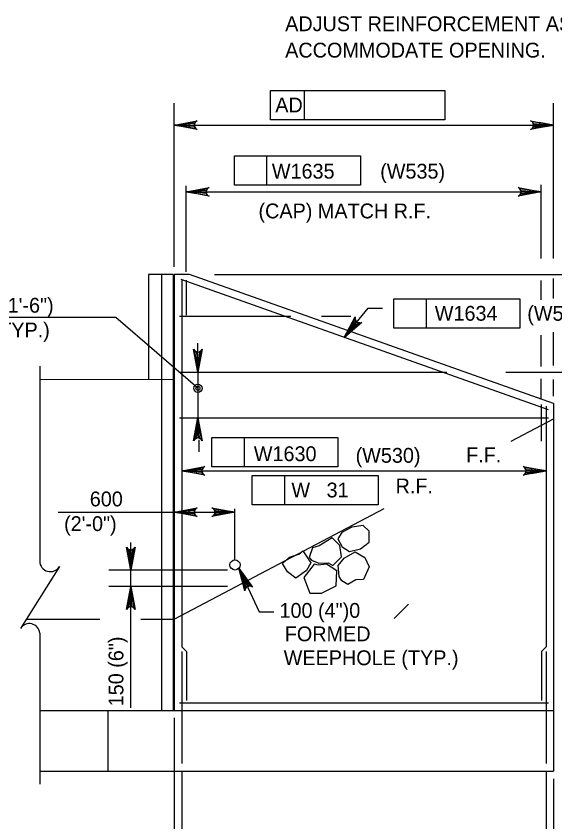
# Model space of a CAD drawing. Extents: x 638340 to 640241, y 295465 to 298435.
# Drawn here: x 638795.5 to 638904.7, y 296169.9 to 296333.1 of the extents above; entities that cross this region are included whole.
import ezdxf

# ---------------------------------------------------------------- set-up
doc = ezdxf.new("R2010")
doc.units = 0
for name, color, linetype in [('10', 7, 'Continuous'), ('3', 7, 'Continuous'), ('4', 7, 'Continuous'), ('5', 7, 'Continuous'), ('6', 7, 'Continuous')]:
    doc.layers.add(name, color=color, linetype=linetype)

# ---------------------------------------------------------------- blocks, each defined once
blk = doc.blocks.new('ROCK')
at = {"layer": '4'}
for points in [[(2.36725, 1.088), (2.2065, 0.82625), (2.378625, 0.506625), (2.66975, 0.3095), (3.128875, 0.403375), (3.48475, 0.6775), (3.4915, 1.123375), (3.25625, 1.36725), (2.783625, 1.308375)], [(1.10175, -0.02725), (1.4015, -0.159125), (1.78825, -0.148875), (1.980875, -0.266), (2.343375, 0.09475), (2.27875, 0.5505), (1.969375, 0.883), (1.4225, 0.553625), (1.152875, 0.479), (1.0105, 0.082)], [(0.74675, 0.359875), (0.882, 0.16), (1.072875, -0.144), (0.892, -0.457375), (0.448125, -0.758625), (0.1, -0.49325), (-0.095, -0.146375), (0.202875, 0.1025), (0.579125, 0.219875)], [(2.231375, -0.71725), (2.2025, -0.266375), (2.45475, 0.037125), (2.9085, 0.28875), (3.2995, 0.047625), (3.46875, -0.344), (3.231625, -0.855), (2.92, -0.860375), (2.5765, -1.054625), (2.340375, -0.904375)], [(1.2085, -0.192875), (0.778375, -0.737625), (1.008375, -1.391375), (1.48725, -1.396875), (2.09825, -1.106625), (2.133375, -0.486375), (1.723125, -0.203375), (1.37425, -0.239875)]]:
    blk.add_lwpolyline(points, close=True, dxfattribs=at)

msp = doc.modelspace()

# ---------------------------------------------------------------- linework, layer by layer
at = {"layer": '10'}
for p, q in [((638827.32, 296280.76), (638822.31, 296280.76)), ((638822.31, 296280.76), (638822.31, 296259.5)), ((638824.98, 296280.76), (638824.98, 296192.49)), ((638827.32, 296280.76), (638827.32, 296192.49)), ((638827.57, 296280.76), (638827.57, 296192.49)), ((638830.65, 296280.76), (638827.57, 296280.76)), ((638904.47, 296254.62), (638830.65, 296280.76)), ((638800.3, 296259.59), (638827.32, 296259.48)), ((638904.47, 296254.62), (638904.47, 296180.18)), ((638895.87, 296247), (638904.47, 296251.54)), ((638827.57, 296210.94), (638870.11, 296233.4)), ((638797.55, 296210.94), (638812.47, 296210.94)), ((638820.82, 296210.94), (638827.57, 296210.94)), ((638800.3, 296192.49), (638904.47, 296192.49)), ((638814.1, 296192.49), (638814.1, 296180.18)), ((638800.3, 296180.18), (638904.47, 296180.18))]:
    msp.add_line(p, q, dxfattribs=at)
at = {"layer": '3'}
for p, q in [((638815.71, 296272.08), (638781.51, 296272.08)), ((638832.36, 296257.73), (638815.71, 296272.08)), ((638800.3, 296262.18), (638800.3, 296222.71)), ((638804.28, 296221.64), (638796.37, 296209.07)), ((638800.3, 296208.14), (638800.3, 296177.56))]:
    msp.add_line(p, q, dxfattribs=at)
for radius in [0.833, 0.417]:
    msp.add_circle((638832.36, 296257.72), radius, dxfattribs=at)
for centre, start, end in [((638802.43, 296222.71), 180, 330), ((638798.18, 296207.94), 5.3286, 147.8672)]:
    msp.add_arc(centre, 2.13, start, end, dxfattribs=at)
at = {"layer": '4'}
for p, q in [((638847.09, 296318.02), (638882.4, 296318.02)), ((638847.09, 296312.12), (638847.09, 296318.02)), ((638853.94, 296312.12), (638853.94, 296318.02)), ((638882.4, 296318.02), (638882.4, 296312.12)), ((638827.57, 296282.3), (638827.57, 296315.46)), ((638904.47, 296284), (638904.47, 296315.46)), ((638882.4, 296312.12), (638847.09, 296312.12)), ((638830.52, 296311.03), (638901.52, 296311.03)), ((638839.76, 296304.78), (638865.3, 296304.78)), ((638839.76, 296298.88), (638839.76, 296304.78)), ((638846.35, 296298.88), (638846.35, 296304.78)), ((638865.3, 296304.78), (638865.3, 296298.88)), ((638901.94, 296284), (638901.94, 296298.95)), ((638829.96, 296281.28), (638829.96, 296298.74)), ((638829.96, 296297.5), (638901.94, 296297.5)), ((638865.3, 296298.88), (638839.76, 296298.88)), ((638835.71, 296280.76), (639028.76, 296280.76)), ((638901.94, 296275.67), (638901.94, 296279.53)), ((638904.47, 296275.88), (638904.47, 296279.94)), ((638872.07, 296275.83), (638897.61, 296275.83)), ((638872.07, 296269.93), (638872.07, 296275.83)), ((638878.67, 296269.93), (638878.67, 296275.83)), ((638897.61, 296275.83), (638897.61, 296269.93)), ((638861.98, 296268.04), (638866.86, 296273.94)), ((638866.86, 296273.94), (638869.81, 296273.94)), ((638857.42, 296272.35), (638863.35, 296272.35)), ((638897.61, 296269.93), (638872.07, 296269.93)), ((638901.94, 296262.13), (638901.94, 296268.49)), ((638904.47, 296262.33), (638904.47, 296269.07)), ((638832.36, 296263.93), (638832.36, 296266.88)), ((638832.36, 296260.98), (638832.36, 296251.75)), ((638894.75, 296260.98), (638908.73, 296260.98)), ((638901.94, 296255.62), (638901.94, 296259.65)), ((638904.47, 296256.16), (638904.47, 296259.51)), ((638832.57, 296247.26), (638832.57, 296244.87)), ((638835.21, 296247.75), (638860.74, 296247.75)), ((638835.21, 296241.84), (638835.21, 296247.75)), ((638841.8, 296241.84), (638841.8, 296247.75)), ((638860.74, 296247.75), (638860.74, 296241.84)), ((638860.74, 296241.84), (638835.21, 296241.84)), ((638829.11, 296240.98), (638902.93, 296240.98)), ((638843.36, 296240.04), (638868.9, 296240.04)), ((638843.36, 296234.14), (638843.36, 296240.04)), ((638849.95, 296234.14), (638849.95, 296240.04)), ((638868.9, 296240.04), (638868.9, 296234.14)), ((638868.9, 296234.14), (638843.36, 296234.14)), ((638804.04, 296232.63), (638839.88, 296232.63)), ((638839.87, 296222.97), (638839.87, 296233.28)), ((638818.75, 296192.98), (638818.75, 296226.5)), ((638838.34, 296220.92), (638814.32, 296220.92)), ((638840.65, 296221.26), (638844.79, 296212.48)), ((638838.34, 296217.56), (638814.32, 296217.56)), ((638844.79, 296212.48), (638847.74, 296212.48)), ((638872.15, 296211.13), (638875.02, 296214)), ((638827.57, 296190.95), (638827.57, 296158.28)), ((638829.11, 296180.18), (638829.11, 296158.28)), ((638902.93, 296180.18), (638902.93, 296158.28)), ((638904.47, 296178.65), (638904.47, 296158.28))]:
    msp.add_line(p, q, dxfattribs=at)
for points in [[(638827.57, 296311.03), (638832.23, 296311.9), (638831.87, 296311.66), (638831.69, 296311.34), (638831.64, 296311.03), (638831.69, 296310.72), (638831.87, 296310.41), (638832.23, 296310.16), (638827.57, 296311.03), (638831.87, 296310.41), (638831.69, 296310.72), (638827.57, 296311.03), (638831.64, 296311.03), (638831.69, 296311.34), (638827.57, 296311.03), (638831.87, 296311.66)], [(638904.47, 296311.03), (638899.81, 296310.16), (638900.17, 296310.41), (638900.35, 296310.72), (638900.41, 296311.03), (638900.35, 296311.34), (638900.17, 296311.66), (638899.81, 296311.9), (638904.47, 296311.03), (638900.17, 296311.66), (638900.35, 296311.34), (638904.47, 296311.03), (638900.41, 296311.03), (638900.35, 296310.72), (638904.47, 296311.03), (638900.17, 296310.41)], [(638829.96, 296297.5), (638834.62, 296298.37), (638834.26, 296298.12), (638834.08, 296297.81), (638834.02, 296297.5), (638834.08, 296297.19), (638834.26, 296296.87), (638834.62, 296296.63), (638829.96, 296297.5), (638834.26, 296296.87), (638834.08, 296297.19), (638829.96, 296297.5), (638834.02, 296297.5), (638834.08, 296297.81), (638829.96, 296297.5), (638834.26, 296298.12)], [(638901.94, 296297.5), (638897.28, 296296.63), (638897.64, 296296.87), (638897.82, 296297.19), (638897.88, 296297.5), (638897.82, 296297.81), (638897.64, 296298.12), (638897.28, 296298.37), (638901.94, 296297.5), (638897.64, 296298.12), (638897.82, 296297.81), (638901.94, 296297.5), (638897.88, 296297.5), (638897.82, 296297.19), (638901.94, 296297.5), (638897.64, 296296.87)], [(638861.98, 296268.04), (638864.27, 296272.19), (638864.24, 296271.75), (638864.36, 296271.41), (638864.57, 296271.17), (638864.84, 296271.01), (638865.2, 296270.95), (638865.62, 296271.07), (638861.98, 296268.04), (638865.2, 296270.95), (638864.84, 296271.01), (638861.98, 296268.04), (638864.57, 296271.17), (638864.36, 296271.41), (638861.98, 296268.04), (638864.24, 296271.75)], [(638832.36, 296260.98), (638831.49, 296265.64), (638831.74, 296265.28), (638832.05, 296265.1), (638832.36, 296265.04), (638832.67, 296265.1), (638832.99, 296265.28), (638833.23, 296265.64), (638832.36, 296260.98), (638832.99, 296265.28), (638832.67, 296265.1), (638832.36, 296260.98), (638832.36, 296265.04), (638832.05, 296265.1), (638832.36, 296260.98), (638831.74, 296265.28)], [(638832.36, 296251.75), (638833.23, 296247.09), (638832.99, 296247.45), (638832.67, 296247.64), (638832.36, 296247.69), (638832.05, 296247.64), (638831.74, 296247.45), (638831.49, 296247.09), (638832.36, 296251.75), (638831.74, 296247.45), (638832.05, 296247.64), (638832.36, 296251.75), (638832.36, 296247.69), (638832.67, 296247.64), (638832.36, 296251.75), (638832.99, 296247.45)], [(638829.11, 296240.98), (638833.77, 296241.86), (638833.41, 296241.61), (638833.23, 296241.3), (638833.17, 296240.98), (638833.23, 296240.67), (638833.41, 296240.36), (638833.77, 296240.11), (638829.11, 296240.98), (638833.41, 296240.36), (638833.23, 296240.67), (638829.11, 296240.98), (638833.17, 296240.98), (638833.23, 296241.3), (638829.11, 296240.98), (638833.41, 296241.61)], [(638902.93, 296240.98), (638898.27, 296240.11), (638898.63, 296240.36), (638898.82, 296240.67), (638898.87, 296240.98), (638898.82, 296241.3), (638898.63, 296241.61), (638898.27, 296241.86), (638902.93, 296240.98), (638898.63, 296241.61), (638898.82, 296241.3), (638902.93, 296240.98), (638898.87, 296240.98), (638898.82, 296240.67), (638902.93, 296240.98), (638898.63, 296240.36)], [(638827.57, 296232.63), (638832.23, 296233.5), (638831.87, 296233.25), (638831.69, 296232.94), (638831.64, 296232.63), (638831.69, 296232.31), (638831.87, 296232), (638832.23, 296231.75), (638827.57, 296232.63), (638831.87, 296232), (638831.69, 296232.31), (638827.57, 296232.63), (638831.64, 296232.63), (638831.69, 296232.94), (638827.57, 296232.63), (638831.87, 296233.25)], [(638839.88, 296232.63), (638835.21, 296231.75), (638835.57, 296232), (638835.76, 296232.31), (638835.81, 296232.63), (638835.76, 296232.94), (638835.57, 296233.25), (638835.21, 296233.5), (638839.88, 296232.63), (638835.57, 296233.25), (638835.76, 296232.94), (638839.88, 296232.63), (638835.81, 296232.63), (638835.76, 296232.31), (638839.88, 296232.63), (638835.57, 296232)], [(638818.75, 296220.92), (638817.88, 296225.58), (638818.12, 296225.22), (638818.44, 296225.03), (638818.75, 296224.98), (638819.06, 296225.03), (638819.37, 296225.22), (638819.62, 296225.58), (638818.75, 296220.92), (638819.37, 296225.22), (638819.06, 296225.03), (638818.75, 296220.92), (638818.75, 296224.98), (638818.44, 296225.03), (638818.75, 296220.92), (638818.12, 296225.22)], [(638840.65, 296221.26), (638843.42, 296217.42), (638843.04, 296217.64), (638842.68, 296217.67), (638842.38, 296217.59), (638842.12, 296217.41), (638841.91, 296217.11), (638841.84, 296216.68), (638840.65, 296221.26), (638841.91, 296217.11), (638842.12, 296217.41), (638840.65, 296221.26), (638842.38, 296217.59), (638842.68, 296217.67), (638840.65, 296221.26), (638843.04, 296217.64)], [(638818.75, 296217.56), (638819.62, 296212.9), (638819.37, 296213.26), (638819.06, 296213.44), (638818.75, 296213.5), (638818.44, 296213.44), (638818.12, 296213.26), (638817.88, 296212.9), (638818.75, 296217.56), (638818.12, 296213.26), (638818.44, 296213.44), (638818.75, 296217.56), (638818.75, 296213.5), (638819.06, 296213.44), (638818.75, 296217.56), (638819.37, 296213.26)]]:
    msp.add_lwpolyline(points, dxfattribs=at)
for points in [[(638830.52, 296311.52), (638830.52, 296310.54), (638827.57, 296311.03)], [(638901.52, 296311.52), (638901.52, 296310.54), (638904.47, 296311.03)], [(638864.24, 296270), (638863.48, 296270.63), (638861.98, 296268.04)], [(638831.87, 296263.93), (638832.85, 296263.93), (638832.36, 296260.98)], [(638831.87, 296248.8), (638832.85, 296248.8), (638832.36, 296251.75)], [(638832.06, 296241.48), (638832.06, 296240.49), (638829.11, 296240.98)], [(638899.98, 296241.48), (638899.98, 296240.49), (638902.93, 296240.98)], [(638830.52, 296233.12), (638830.52, 296232.13), (638827.57, 296232.63)], [(638818.26, 296223.87), (638819.24, 296223.87), (638818.75, 296220.92)], [(638841.46, 296218.38), (638842.35, 296218.8), (638840.65, 296221.26)], [(638818.26, 296214.61), (638819.24, 296214.61), (638818.75, 296217.56)]]:
    msp.add_lwpolyline(points, close=True, dxfattribs=at)
msp.add_circle((638839.88, 296221.94), 1.03, dxfattribs=at)
at = {"layer": '5'}
for p, q in [((638829.96, 296279.64), (638829.97, 296272.54)), ((638901.93, 296254.45), (638901.94, 296247))]:
    msp.add_line(p, q, dxfattribs=at)
at = {"layer": '6'}
for p, q in [((638903.44, 296253.35), (638828.94, 296279.74)), ((638829.11, 296279.74), (638829.11, 296205.36)), ((638828.6, 296272.35), (638851.19, 296272.35)), ((638828.6, 296260.98), (638882.8, 296260.98)), ((638902.93, 296254.08), (638902.93, 296205.36)), ((638828.6, 296251.75), (638903.44, 296251.75)), ((638829.11, 296205.36), (638830.05, 296204.43)), ((638829.11, 296204.43), (638829.11, 296181.72)), ((638830.05, 296204.43), (638830.05, 296194.48)), ((638902.93, 296205.36), (638902, 296204.43)), ((638902, 296204.43), (638902, 296194.48)), ((638902.93, 296204.43), (638902.93, 296181.72)), ((638828.6, 296194.03), (638903.44, 296194.03))]:
    msp.add_line(p, q, dxfattribs=at)

# ---------------------------------------------------------------- block references
at = {"layer": '4', "xscale": 4.921475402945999, "yscale": 4.921475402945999, "rotation": 0.8865726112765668}
msp.add_blockref('ROCK', (638849.96, 296222.97), dxfattribs=at)

# ---------------------------------------------------------------- texts
at = {"layer": '3'}
for s, height, p in [('450 (1\'-6")', 3.0001, (638784.65, 296273.04)), ('(TYP.)', 3, (638790.75, 296268.03)), ('100 (4")0', 3, (638848.9, 296211.24)), ('FORMED', 3, (638849.97, 296206.49))]:
    msp.add_text(s, height=height, dxfattribs=at).set_placement(p)
at = {"layer": '4'}
for s, height, p in [('ADJUST REINFORCEMENT AS NECESSARY TO', 3.0001, (638850.05, 296330.05)), ('ACCOMMODATE OPENING.', 3.0001, (638850.05, 296324.71)), ('AD', 3, (638848.04, 296313.6)), ('W1635', 3, (638847.35, 296300.19)), ('(W535)', 3, (638869.31, 296300.19)), ('(CAP) MATCH R.F.', 3.0001, (638844.64, 296292.14)), ('W1634', 3, (638880.38, 296271.41)), ('(W534)', 3, (638899.12, 296271.41)), ('W1630', 3, (638843.69, 296242.97)), ('(W530)', 3, (638864.33, 296242.64)), ('F.F.', 3, (638886.73, 296242.75)), ('W   31', 3, (638851.31, 296235.62)), ('R.F.', 3, (638872.43, 296236.45)), ('600', 3, (638810.44, 296233.81)), ('(2\'-0")', 3, (638805.23, 296228.81)), ('WEEPHOLE (TYP.)', 3.0001, (638849.75, 296201.65))]:
    msp.add_text(s, height=height, dxfattribs=at).set_placement(p)
msp.add_text('150 (6")', height=3, rotation=90, dxfattribs=at).set_placement((638817.25, 296193.31))

doc.saveas('drawing.dxf')
